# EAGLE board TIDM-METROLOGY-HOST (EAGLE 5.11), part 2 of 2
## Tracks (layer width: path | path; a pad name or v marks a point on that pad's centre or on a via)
+12V  (via drill 0.5)
  Top 0.254: R30.2 17.35,44.13 17.27,44.2 C53.1 18.87,44.28 20.32,45.73 21.71,45.73 21.96,45.97 21.96,46.62 21.84,46.74 C15.+
  Top 0.406: R30.2 17.53,41.92 17.34,41.73 T1.E 16.59,39.46 16,38.87 16,37.09 17.27,35.82 27.71,35.82 29.09,37.2 29.09,38.23 29.08,38.23 | 29.08,38.23 28.96,38.36 | 29.08,38.23 U2.8 | D3.2 20.07,53.35 19.66,52.94 D4.2 19.66,51.72 v18.54,52.84 | 22.1,46.74 C15.+ v19.71,46.73
  Bottom 0.406: v18.54,52.84 18.54,47.76 v19.71,46.73
+12V1
  Top 0.406: CON1.7 10.67,50.55 11.94,51.82 11.94,55.63 12.19,55.89 14.73,55.89 15.49,55.12 22.61,55.12 22.86,54.87 22.86,53.6 23.11,53.35 24.38,53.35 24.41,53.32 D3.1
+12V3
  Top 0.406: CON1.4 13.21,54.62 14.82,54.62 16.4,53.04 16.4,51.43 16.51,51.31 16.38,51.19 D4.1
-12V  (via drill 0.5)
  Top 0.254: C53.2 18.03,46.16 18.03,45.98 18.64,45.38 v18.64,45.34 | R31.1 21.92,41.59 v21.34,42.17 | D7.1 21.31,48.49 21.84,49.03 21.84,50.04 C22.-
  Top 0.406: R31.1 25.83,41.59 25.91,41.66 25.98,41.59 R28.2 26.16,41.66 26.54,42.04 U2.5 | C53.2 17.96,46.16 18.8,47 18.8,48.27 18.92,48.39 D7.1
  Bottom 0.254: v21.34,42.17 20.57,42.17 v18.64,45.34
A0CLK  (via drill 0.41, 0.5)
  Top 0.254: U1.17 21.88,70.4 23.88,72.4 28.57,72.4 28.96,72.78 v28.98,72.78 | R82.2 86.61,86.37 85.6,85.35 77.98,85.35 74.17,89.16 46.23,89.16 45.97,88.91 v45.97,88.65
  Bottom 0.254: v45.97,88.65 45.97,88.78 44.83,89.92 42.16,89.92 41.15,88.91 41.15,84.33 36.07,79.25 36.07,75.95 34.39,74.28 30.45,74.28 28.96,72.78 | 28.96,72.78 | v28.98,72.78 28.96,72.78
A0CS  (via drill 0.41, 0.5)
  Top 0.254: 73.91,77.22 73.89,77.25 v73.89,77.37 | 73.91,77.48 73.89,77.45 v73.89,77.37 | R81.2 88.39,85.63 87.22,84.46 83.07,84.46 83.04,84.49 83.02,84.46 v82.83,84.46 | v73.89,77.37 73.81,77.37 72.9,76.46 72.9,72.9 72.39,72.4 55.63,72.4 49.28,66.05 48.77,65.54 37.85,65.54 36.99,66.4 U1.51
  Bottom 0.254: v82.83,84.46 78.03,84.46 77.7,83.88 77.72,79 77.72,78.87 76.22,77.37 v73.89,77.37
A0SIMO  (via drill 0.6)
  Top 0.254: R106.1 80.52,100.84 v79.76,100.08 v79.76,91.19 79.76,87.13 80.52,86.37 84.33,86.37 84.84,86.87 R83.2 | R77.2 95.5,85.86 v96.77,84.59 | U1.21 22.92,68.4 24.89,70.36 32.77,70.36 33.53,71.13 33.53,74.68 v32.77,75.44 | v45.72,91.19 v77.72,91.19
  Bottom 0.254: v96.77,84.59 95.25,86.11 95.25,97.8 94.49,98.56 88.14,98.56 86.61,100.08 v79.76,100.08 | v32.77,75.44 34.54,75.44 35.05,75.95 35.05,79 40.64,84.59 40.64,89.41 41.66,90.43 44.96,90.43 v45.72,91.19 | v77.72,91.19 v79.76,91.19
A0SOMI  (via drill 0.5, 0.6)
  Top 0.254: U1.22 23.19,67.9 25.15,69.86 32.89,69.86 34.04,70.8 v34.04,76.67 | 83.06,87.38 R84.2 83.15,87.29 83.06,87.38 | v92.2,84.33 93.73,85.86 R78.2 93.73,87.64 | v77.22,87.38 74.93,89.67 45.21,89.67 44.2,90.68 v44.2,91.7 | R107.1 81.45,91.36 v81.53,87.38 83.06,87.38
  Bottom 0.254: v92.2,84.33 89.92,87.38 v81.53,87.38 v77.22,87.38 | v34.04,76.67 34.04,78.75 40.13,84.84 40.13,89.92 41.91,91.7 v44.2,91.7
ACT_PUL  (via drill 0.5)
  Top 0.254: U$1.P$17 48.73,26.71 47.75,27.69 47.75,30.36 v46.86,31.12
  Top 0.406: R75.1 48.77,49.28 48.26,48.77 ACT.1 48.24,47.52 47.48,47.52 45.21,45.25 LED1.K
  Bottom 0.406: LED1.K 43.94,42.93 41.4,42.93 40.13,41.66 40.13,37.34 41.15,36.33 COMMS.8 42.93,33.79 45.59,31.12 v46.86,31.12
AFE_INT  (via drill 0.5)
  Top 0.254: U$1.P$18 49.4,26.04 48.62,26.06 47.12,27.56 47.12,29.6 v46.81,29.84 | ISO3.7 63.12,49.15 v62.74,48.77 | v62.48,37.6 62.47,40.75 v62.22,41
  Bottom 0.254: v62.48,37.6 60.2,39.63 53.34,39.63 51.82,38.11 51.82,30.99 50.67,29.85 46.99,29.85 46.98,29.84 v46.81,29.84 | v62.22,41 62.22,41.02 62.23,41.03 64.64,41.03 65.53,41.92 65.53,48.27 65.02,48.77 v62.74,48.77
AGND_AFE  (via drill 0.41, 0.5, 0.6)
  Top 0.406: R33.1 R34.2 | JMP1.1 91.19,16.26 90.93,16.52 C33.1
  Top 0.813: R47.2 42.42,12.45 42.51,12.54 | 42.51,12.54 R53.1 33.11,9.4 R24.1 | C14.1 42.51,15.08 42.67,14.99 42.51,14.9 42.51,12.54
  Bottom 0.254: 63.5,22.1 v63.5,30.99
  other vias: 64.52,16.01 83.57,15.25 38.1,14.99 42.42,19.56 46.48,2.29 46.48,9.66 58.67,19.56 58.67,16.26 72.9,16.26 77.22,16.01 78.49,2.8 69.85,1.02 57.15,1.28 95.76,1.28 95.25,11.94 98.81,17.28 86.87,18.55 69.85,24.64 60.2,27.06
  pour Top: 36.07,0.01 36.07,20.71 54.86,20.71 54.83,29.81 59.01,29.93 59.69,30.74 61.98,34.3 62.74,34.3 71.04,26 71.08,24.98 71.12,21.85 84.84,21.85 88.65,18.29 100.58,18.29 100.58,13.47 97.28,13.47 97.03,0.26
  pour Bottom: 36.07,0.26 36.07,20.58 55.37,20.58 55.37,29.98 58.93,29.72 60.96,32.52 61.98,34.04 63.5,34.04 70.87,26.17 70.99,23.88 71.12,21.85 85.09,21.85 88.65,18.29 99.82,18.29 99.82,14.23 96.77,14.23 97.03,0.26
AGND_APP
  Top 0.254: U1.15 21.86,71.4 22.35,71.89 22.35,72.4 21.84,72.9 | 21.84,72.9 21.08,72.9 21.07,72.9 U1.12 18.8,72.9 17.14,74.94 16,74.94 C32.- 15.88,75.31 15.58,75.61 C35.1 13.72,75.7 8.64,75.7 8.25,76.08 8.25,77.09 8.22,77.13 R4.2 | U1.83 30.95,79.32 30.48,79 28.96,79 27.43,77.48 26.16,77.48 22.02,73.05 21.84,72.9
APP_INT  (via drill 0.5)
  Top 0.254: U1.34 26.45,63.79 v26.09,63.1 | 63.25,55.38 63.25,56.39 63.19,56.45 ISO3.2 63.12,58.93 63.12,61.47 | 63.12,61.47 63.12,61.6 64.01,62.49 64.01,64.01 COMMS_APP.2 | v56.39,57.41 56.39,59.7 57.66,60.97 62.48,60.97 62.99,61.47 63.12,61.47
  Bottom 0.254: v26.09,63.1 26.19,63.1 26.29,63 26.39,63.1 27.68,63.1 32.61,58.17 55.88,58.17 56.39,57.66 v56.39,57.41
AVCC_AFE  (via drill 0.6)
  Top 0.254: U$1.P$5 61.59,24.76 63.5,26.68 C12.2
  Top 0.305: v67.56,27.05 C11.+ | 67.69,27.05 69.09,28.45 69.09,30.57 R2.2
  Top 0.406: C11.+ 65.41,27.05 65.11,27.35 C12.2
  Top 0.61: D22.C 53.34,9.91 v52.07,11.18 | v66.29,7.37 65.45,6.53 D24.C | D26.C 75.44,11.18 v74.68,11.94 | D28.C 87.04,8.64 v85.09,8.64 | v67.56,27.05 67.69,27.05
  Bottom 0.61: v52.07,11.18 55.88,7.37 v66.29,7.37 70.1,7.37 74.68,10.42 | v85.09,8.64 76.45,8.64 74.68,10.42 | 74.68,10.42 v74.68,11.94 74.68,13.47 74.42,17.02 74.42,18.8 71.37,21.85 71.37,24.9 70.36,25.91 68.7,25.91 v67.56,27.05
AVCC_APP
  Top 0.254: U1.11 19.57,73.4 19.3,73.67 19.3,76.21 17.53,77.98 | C35.2 14.06,77.31 14.99,78.24 16,78.24 C32.+ 16.64,78.11
  Top 0.61: R3.2 18.45,78.91 17.53,77.98 16,77.98 C32.+
CCA  (via drill 0.5)
  Top 0.254: U1.39 28.95,62.98 30.48,62.24 41.66,62.24 43.43,64.01 50.04,64.01 50.29,64.27 54.61,68.59 v77.47,68.59 | R79.2 91.95,86.87 v92.71,86.11
  Bottom 0.254: v92.71,86.11 94.23,84.59 94.23,73.16 90.17,69.09 77.98,69.09 v77.47,68.59 77.34,68.46
COM0  (via drill 0.41, 0.5)
  Top 0.254: U1.30 24.45,66.62 25.91,68.08 v30.1,67.98 | v66.04,98.56 65.79,98.56 65.28,98.05 45.72,98.05 41.4,93.73 41.4,89.67 42.42,88.65 v43.18,88.65
  Bottom 0.254: v30.1,67.98 30.1,68.71 31.11,69.73 31.37,69.98 35.18,69.98 36.58,71.51 36.58,79 41.66,84.08 41.66,88.02 42.29,88.65 v43.18,88.65 | LCD1.P$18 66.29,98.81 v66.04,98.56
COM1  (via drill 0.41, 0.5)
  Top 0.254: U1.31 24.95,66.1 25.91,67.06 30.99,67.06 v31.62,67.59 | v67.56,98.05 67.06,98.05 66.29,97.29 45.97,97.29 42.16,93.48 42.16,90.43 42.93,89.67 43.69,89.67 44.07,89.11 44.08,87.64 v44.7,87.28
  Bottom 0.254: v44.7,87.28 44.7,84.84 38.1,78.24 38.1,70.62 35.08,67.59 v31.62,67.59 | LCD1.P$17 68.83,99.32 v67.56,98.05
COM2  (via drill 0.41, 0.5)
  Top 0.254: U1.32 25.45,65.84 26.16,66.55 32.26,66.55 32.77,67.06 32.77,68.08 v32.26,68.59 | 44.96,99.32 40.39,94.75 40.39,87.64 41.66,86.37 v43.18,86.37 | 44.96,99.32 45.47,99.83 | v71.37,99.32 71.12,99.32 70.36,100.08 45.72,100.08 44.96,99.32
  Bottom 0.254: v32.26,68.59 32.77,68.08 33.63,68.11 34.83,68.11 37.59,70.87 37.59,78.49 43.18,84.08 v43.18,86.37 | v71.37,99.32 LCD1.P$16
COM3  (via drill 0.41, 0.5)
  Top 0.254: U1.33 25.95,65.58 26.42,66.05 32.51,66.05 33.53,67.06 33.53,68.84 33.27,69.09 v33.33,69.09 | 45.21,98.56 45.72,99.07 | v71.88,96.53 68.83,99.57 46.23,99.57 45.21,98.56 | v43.24,87.53 41.77,87.53 40.89,88.4 40.89,94.24 45.21,98.56
  Bottom 0.254: LCD1.P$15 73.91,98.56 v71.88,96.53 | v33.33,69.09 35.05,69.09 37.08,71.25 37.08,78.75 42.16,83.83 42.16,87.13 42.55,87.51 43.05,87.51 43.07,87.53 v43.24,87.53
D+  (via drill 0.5)
  Top 0.254: USB2.3 13.13,89.49 v12.45,90.18
  Bottom 0.254: R7.2 9.65,89.16 9.69,89.12 IC7.4 9.84,89.23 9.8,89.26 9.86,89.31 9.86,89.92 10.11,90.18 v12.45,90.18
D-
  Bottom 0.254: 10.92,86.37 R35.2 10.92,86.11 10.89,86.15 IC7.1 10.92,88.14 11.43,88.14 11.96,88.73 14.73,88.73 15.13,88.26 USB2.2
DGND_AFE  (via drill 0.3, 0.41, 0.5)
  Top 0.254: v73.66,48.77 C52.1
  Top 0.406: ZD1.1 18.41,30.1 19.3,29.22 22.86,29.22 23.11,28.96 23.19,29.04 C26.1
  Top 0.61: 17.65,24.92 17.6,26.17 17.78,26.42 18.32,26.97 IC3.3 | 17.65,24.92 C25.1 | IC3.3 22.13,26.97 22.1,26.93 | IC3.3 IC3.2 23.11,28.96 23.37,29.22 C26.1 23.11,29.22 23.11,30.49 23.88,31.25 27.18,31.25 27.94,30.49 C23.- | 17.65,24.92 17.61,24.87 ZD2.1 14.2,24.87 13.46,24.14 | R1.1 11.18,17.02 13.46,19.31 13.46,21.85
  Top 0.813: R26.1 21.42,12.62 C4.- 14.61,13.21 R1.1
  Bottom 0.254: v73.66,48.77 73.41,48.77 72.9,49.28
  other vias: 42.16,55.63 76.96,26.93 74.17,51.31 96.77,35.31 19.05,28.96 76.96,35.57 67.06,50.55 54.86,46.23 35.56,25.66 41.66,33.79 47.5,55.63 31.24,34.8 35.31,50.55 41.4,40.65 36.07,37.09 70.74,28.96 50.42,32.01 50.42,33.15 59.69,41.05 60.2,36.33 61.72,39.38 91.19,24.39
  pour Top: 9.14,21.34 9.14,34.55 29.97,34.8 31.24,36.84 31.24,57.41 59.18,57.28 59.18,54.62 78.49,54.87 78.23,49.79 69.6,49.54 69.6,40.77 87.88,40.9 87.88,43.19 99.82,43.19 99.95,38.23 99.82,19.06 88.9,19.06 85.09,22.61 78.36,22.61 72.01,22.74 71.88,26.42 62.87,35.31 61.98,35.31 58.93,31.25 54.1,30.99 54.1,21.34
  pour Bottom: 9.14,21.34 9.14,34.55 31.24,34.55 31.24,57.41 59.05,57.41 59.05,54.36 78.1,54.23 77.85,51.57 69.47,47.63 69.6,41.15 86.87,41.15 86.87,43.19 99.82,43.19 100.08,19.31 88.65,19.31 85.34,22.61 71.88,22.87 71.88,26.42 71.12,26.93 70.87,27.18 64.14,34.5 63.63,35.01 62.48,35.06 61.72,34.8 58.17,30.74 54.1,30.74 54.1,21.34
DGND_APP  (via drill 0.3, 0.41, 0.5, 0.6)
  Top 0.254: U1.90 27.45,81.56 28.08,82.43 28.09,83.27 26.04,84.76 26.04,85.22 26.16,85.35 | 26.16,85.35 26.58,85.77 | C45.1 94.07,69.69 94.74,70.36 94.74,71.38 C44.- | C20.- 20.32,60.46 | 26.16,85.35 C7.-
  other vias: 2.03,76.46 18.57,74.43 19.3,58.43 97.28,69.6 90.8,67.82 30.28,76.66 74.68,93.99 85.85,74.17 73.41,86.87 53.59,93.73 56.13,93.73 58.42,93.73 90.93,84.08 65.28,83.32 44.9,88.38 37.08,88.65 21.43,81.14 31.5,86.11 47.5,98.81 18.54,92.97 37.85,104.15 22.18,74.45 75.79,69.4 33.91,66.17 31.88,73.41 73.13,61.14 77.72,63.76 65.74,57.05 45.97,72.65 52.32,60.97 57.91,58.2
  pour Top: 100.08,100.59 88.9,100.59 88.9,112.02 10.92,112.02 10.92,100.84 0.25,100.84 0.25,68.84 16,68.84 16,57.54 30.61,57.54 30.61,58.17 59.82,58.17 59.79,56.16 68.58,56.14 80.01,55.89 85.85,60.2 100.33,60.2
  pour Bottom: 0.32,100.83 0.32,69.08 15.75,69.09 15.75,55.89 27.18,55.89 31.24,58.68 31.75,58.17 60.1,58.17 60.05,55.02 68.07,55.12 78.74,54.87 85.85,60.2 100.33,60.2 100.33,100.84 88.9,100.84 88.9,112.02 10.92,112.02 10.92,100.83
DVCC_AFE  (via drill 0.5, 0.6)
  Top 0.254: 79.12,52.96 ISO2.8 79.12,51.95 76.96,49.79 76.96,49.03 77.05,48.94 C52.2 | U$1.P$16 51.38,27.36 50.67,28.07 50.67,28.45 | ISO3.8 64.39,53.66 64.38,53.67 64.39,53.69 64.39,53.73 66.29,55.58 70.13,55.58 70.99,54.74 70.99,53.47 71.12,53.35 | ISO1.8 71.06,52.78 71.12,52.84 71.12,53.35 | C55.2 71.21,53.43 71.12,53.35
  Top 0.305: DVCC1.4 72.64,33.79 75.95,30.49 v76.45,30.14 76.45,28.96 75.44,27.95 72.39,27.95 71.88,28.45 71.88,29.81 R2.1
  Top 0.406: 85.85,25.91 JTG_PWR1.2 85.76,24.81 R61.1 | 39.62,49.79 39.62,50.3 39.29,50.63 C54.2 R39.1 36.91,48.7 36.83,48.77 36.07,48.77 35.69,49.15 U5.8 32.89,49.15 32.26,49.79 32.26,52.08 R73.2 | v49.1,27.62 48.9,27.56 48.9,28.45 | 41.31,28.2 v42.07,28.08 | 64.39,53.73 59.82,53.73 59.44,54.11 57.4,54.11 56.13,52.84 45.72,52.84 | 41.91,47.76 R72.2 | 45.72,52.84 44.96,52.84 OK2.1 | 41.4,49.79 44.96,49.79 45.97,50.81 45.97,52.58 45.72,52.84 | 48.9,28.45 48.77,29.22 C9.+ 48.77,28.45 48.9,28.45 | C10.2 50.67,28.45 48.9,28.45 | C55.2 72.9,54.36 73.66,55.12 78.74,55.12 79.12,54.74 79.12,52.96
  Top 0.61: PWR1.2 41.31,26.69 41.31,28.2 41.31,32.61 38.64,35.28 38.64,39.09 38.61,39.12 38.65,39.16 R37.1 38.65,41.96 v39.12,42.42 | v40.13,44.71 40.13,45.47 41.91,47.25 41.91,47.76 41.91,49.03 41.4,49.79 39.62,49.79 R27.2 | DVCC1.4 DVCC1.3 DVCC1.2 DVCC1.1 | C52.2 77.05,48.86
  Bottom 0.305: v76.45,30.14 76.2,30.49
  Bottom 0.406: JTG_PWR1.2 86.61,25.66 | v42.07,28.08 46.48,28.07 48.26,28.07 v49.1,27.62 | OK1.1 51.56,47 48.77,49.79 48.77,52.58 47.24,54.11 OK2.1
  Bottom 0.61: v40.13,44.71 39.12,43.69 v39.12,42.42 | 49.22,27.49 49.15,27.56 | v49.1,27.62 49.22,27.49 | 49.22,27.49 49.53,27.31 55.12,27.31 57.66,29.85 58.93,29.85 61.6,32.52 65.02,32.52 | 65.02,32.52 80.64,32.52 82.55,30.61 82.55,27.95 84.58,25.91 JTG_PWR1.2 | 65.02,32.52 DVCC1.1
DVCC_APP  (via drill 0.41, 0.5, 0.6)
  Top 0.254: 27.94,80.52 27.95,80.52 U1.89 27.95,81.04 28.96,82.05 v28.96,82.81 | C7.+ 28.7,85.35 28.28,85.77 C8.2 | 20.19,63.38 C20.+ 20.32,63.51 | 20.32,63.51 20.65,63.84 20.65,66.35 U1.25 20.65,63.83 20.32,63.51 | C21.2 18.63,62.83 18.8,63 19.3,63.51 20.32,63.51 | RF4.9 92.07,68.46 92.46,68.84 92.37,68.93 C45.2 92.37,69.69 91.69,70.36 91.69,71.13 91.82,71.25 C44.+ | R3.1 20.15,81.37 20.07,81.29 20.22,81.13 | 28.83,85.27 28.27,85.83 28.27,87.56 28.19,87.64 | v43.43,75.44 43.18,75.44 40.63,72.9 U1.64 | ISO1.1 71.06,57.98 71.21,57.83
  Top 0.406: 92.46,68.84 92.46,68.08 92.96,67.57 99.57,67.57 100.08,67.06 100.08,60.97 99.06,59.95 82.8,59.95 80.83,57.98 | 80.83,57.98 ISO2.1 79.19,57.98 79.25,57.92 79.12,57.79 79.12,56.55 78.71,56.14 73.91,56.14 73.15,56.9 | 28.83,85.27 28.83,82.94 v28.96,82.81 | ISO3.1 64.39,56.27 64.52,56.14 72.39,56.14 73.15,56.9 | 80.77,59.7 C50.2 80.77,57.98 80.83,57.98 | 73.15,56.9 C2.2 71.21,57.83
  Top 0.61: 28.19,87.64 C8.2 28.28,89.25 v28.45,89.41 | 91.69,71.13 90.42,71.13 v89.92,71.89 | 18.8,63 16.51,63 16,62.49 16,57.92 17.27,56.9 29.21,56.9 30.99,58.68 | 30.99,58.68 31.24,58.93 | v84.58,72.4 83.82,73.16 75.69,73.16 75.18,72.65 v75.18,72.4 | 20.07,81.79 20.07,80.27 v20.32,80.02 | v48.57,61.07 48.51,60.2 47.75,59.44 31.75,59.44 30.99,58.68 | R14.1 17.44,85.44 20.07,82.81 20.07,81.79 | 20.07,81.79 20.15,81.71 R3.1
  Bottom 0.254: 41.66,74.17 41.55,74.28
  Bottom 0.406: 41.55,74.28 42.27,74.28 v43.43,75.44
  Bottom 0.61: v28.45,89.41 28.45,91.19 30.99,93.73 30.99,96.27 33.4,98.68 DVCC2.2 37.34,98.56 | 89.66,72.14 v89.92,71.89 89.92,72.14 89.66,72.4 v84.58,72.4 | 48.26,72.4 v75.18,72.4 | 48.26,72.4 47.24,73.41 | 47.24,73.41 46.65,74.01 C6.2 41.82,74.01 41.66,74.17 C5.+ | 48.26,72.4 48.51,72.14 v48.57,61.07 | 47.24,73.41 47.24,95.38 44.2,98.43 37.47,98.43 37.34,98.56 | 37.34,98.56 DVCC2.1 39.8,103.43 39.8,108.72 | v20.32,80.02 27.69,80.02 28.96,81.29 v28.96,82.81 | 39.8,108.72 JTG_PWR2.2 | 39.8,108.72 PWR2.2
DVCC_APP_EXT
  Top 0.406: R15.1 35.18,95.38 34.29,96.53 34.29,101.35 34.8,101.86 34.8,102.11 35.81,103.13 38.86,103.13 PWR2.3
DVCC_APP_PL  (via drill 0.5, 0.6)
  Top 0.406: 87.88,75.95 ZD3.C 87.87,75.93 87.63,75.7 85.6,75.7 C36.+ | C37.1 82.55,81.03 82.3,80.78 77.47,80.78
  Top 0.61: v78.49,78.24 83.06,78.24 | 83.06,78.24 C36.+ | 82.3,80.78 82.3,79 83.06,78.24 | 77.47,80.78 v75.95,82.3 | v75.95,99.07 74.17,100.84 44.2,100.84 42.04,103 44.45,103 44.45,109.73 42.93,111.26 PWR2.1
  Bottom 0.61: U$2.VO+ 75.95,70.36 77.47,71.89 77.47,76.71 v78.49,78.24 | v75.95,99.07 76.2,98.81 75.95,98.56 v75.95,82.3
DVCC_FET1
  Bottom 0.61: JTG_PWR1.1 96.27,23.37 98.3,25.41 98.3,37.09 97.03,38.36 81.53,38.36 JTAG1.2
DVCC_FET2
  Top 0.406: JTAG2.2 32.26,100.34 32.26,109.73 33.78,111.26 JTG_PWR2.1
DVCC_PL
  Top 0.406: IC3.5 24.35,24.35 24.56,24.57 R23.2
  Top 0.61: IC3.5 24.6,24.35 25.15,24.9 25.15,28.96 25.07,29.04 C26.2
  Top 0.813: C26.2 25.74,28.45 28.96,28.45 29.97,29.47 29.97,33.28 29.72,33.53 | 29.72,33.53 27.69,33.53 | 27.69,33.53 27.51,33.53 C23.+ | ZD1.2 22.45,33.53 27.69,33.53 | PWR1.1 33.27,33.53 29.72,33.53
GND1
  Top 0.406: C22.+ 24.64,50.04 24.77,49.91 C15.- 24.64,46.74 24.77,46.61 U5.3 30.35,46.61 30.73,47 30.73,51.06 30.1,51.69 D1.1 30.2,51.8 30.23,51.82 30.09,51.96 30.09,55.07 29.17,55.98 16.33,55.98 15.09,57.23 15.09,57.31 CON1.5
  Bottom 0.813: CON1.G1 11.94,39.12 7.62,39.12 5.08,42.68 5.08,59.95 9.47,64.34 CON1.G2 11.94,64.52 13.21,63.25 CON1.5
HFIN
  Top 0.254: Q1.2 Q1.4 32.51,85.1 30.45,83.03 U1.84
  Bottom 0.406: Q1.4 32.77,85.22 33.66,84.84 C48.1
HFOUT
  Top 0.254: U1.85 29.95,84.06 30.73,84.84 30.73,87.13 31.75,88.14 32.77,88.14 Q1.1 Q1.3
  Bottom 0.254: 36.83,92.21 C47.1
  Bottom 0.406: 36.83,92.21 34.16,92.21 32.77,90.81 Q1.3
I1+
  Top 0.254: C30.1 63.5,22.87 63.25,22.61 | U$1.P$1 61.92,22.16 62.48,21.6 63.25,21.6 63.75,22.1
  Top 0.406: 62.99,20.33 C17.1 | R17.1 63.08,20.24 62.99,20.33 | 62.99,20.33 62.99,21.34 63.75,22.1 63.75,22.87 C30.1
I1-
  Top 0.254: 65.28,22.87 65.37,22.96 | 65.35,23.19 65.28,23.12 65.37,23.03 C30.2 65.28,22.87 | U$1.P$2 62.06,22.81 63.03,23.79 65.1,23.76 65.35,23.52 65.35,22.93 65.28,22.87
  Top 0.406: R18.1 65.7,19.98 65.79,20.07 65.7,20.16 C18.2 65.7,20.49 65.79,20.58 65.37,21 C30.2
IN+
  Top 0.254: 82.8,19.06 72.14,19.06 66.53,24.76 63.31,24.76 61.98,23.46 U$1.P$3
  Top 0.406: R20.2 82.13,14.4 82.04,14.48 82.04,16.52 C31.1 82.13,17.62 82.8,18.29 82.8,19.06 C34.1
IN-
  Top 0.254: 84.33,19.06 C34.2 85.34,19.06 85.6,19.31 85.6,19.82 85.09,20.33 71.88,20.33 66.8,25.41 63.25,25.41 61.84,24.1 U$1.P$4
  Top 0.406: R21.2 85,16.17 85.09,16.26 85,16.35 C33.2 85.09,16.52 85.09,17.79 84.42,18.46 C34.2
L_APP
  Top 0.813: U$2.L 87.63,52.58 82.3,47.25 82.42,47.12 R5.2 85.72,47.12 89.15,50.55 90.93,50.55 91.44,51.06 91.44,55 92.84,56.39 L2.MP
LCDCAP
  Top 0.254: U1.29 23.95,62.42 24.89,61.47 25.4,61.47 C51.+
LINE
  Top 0.61: L1.MP 8.13,4.4 L5.1
LINE_A
  Top 0.61: R1.2 7.7,6.86 L5.2
  Top 0.813: R38.1 34.93,3.82 C49.1
  Bottom 0.813: R1.2 31.88,6.86 C49.1
M_SIMO  (via drill 0.41, 0.7)
  Top 0.254: U1.18 22.14,69.9 24.13,71.89 30.23,71.89 v30.86,72.52 | ISO2.3 v76.58,60.46 76.58,60.58 73.15,64.01 68.83,64.01 67.82,63 COMMS_APP.5
  Bottom 0.254: 76.58,60.33 v76.58,60.46 76.45,60.46 73.91,57.92 62.99,57.92 61.98,58.93 35.56,58.93 27.94,66.55 27.94,69.35 30.86,72.27 v30.86,72.52
M_SOMI  (via drill 0.41, 0.7)
  Top 0.254: U1.19 22.4,69.4 24.38,71.38 30.99,71.38 v31.95,72.24 | ISO2.2 77.85,60.2 v78.49,60.84
  Bottom 0.254: v31.95,72.24 31.9,72.29 28.45,68.84 28.45,67.06 36.07,59.44 62.23,59.44 63.25,58.43 65.79,58.43 70.1,62.74 COMMS_APP.7 76.71,62.74 78.49,60.97 v78.49,60.84
MSPI_CLK  (via drill 0.41, 0.5)
  Top 0.254: U1.20 22.66,68.9 24.64,70.87 32.26,70.87 v32.66,71.42 | v64.01,59.26 65.25,59.29 65.79,59.7 68.08,59.7 68.46,59.32 68.46,58.05 68.39,57.98 | 68.45,58.04 ISO1.3 68.39,57.98 | 68.39,57.98 68.33,57.92
  Bottom 0.254: v32.66,71.42 31.98,71.35 29.2,68.59 29.2,67.33 36.58,59.95 63.25,59.95 64.01,59.19 v64.01,59.26 | v64.01,59.26 63.75,59.26 63.5,59.44 | COMMS_APP.3 65.28,60.46 v64.01,59.26
MSPI_CS  (via drill 0.5)
  Top 0.254: U1.35 26.95,61.7 30.23,60.2 42.67,60.2 44.45,61.98 61.98,61.98 COMMS_APP.1 | ISO1.2 69.72,59.57 69.09,60.2 64.77,60.2 v64.26,60.71
  Bottom 0.254: v64.26,60.71 64.26,61.22 COMMS_APP.1
N$1
  Top 0.61: L6.2 18.89,3.99 R26.2
N$2
  Top 0.406: R36.1 28.96,54.11 28.7,53.85 28.7,52.33 28.19,51.82 D1.2 26.67,51.82 26.67,48.27 27.05,47.88 U5.2
N$3
  Top 0.406: R28.1 26.16,39.63 26.29,39.5 U2.7
N$4
  Top 0.406: R29.1 29.46,44.2 30.73,42.93 30.73,41.02 30.5,40.78 29.33,40.78 29.21,40.9 29.15,40.84 U2.6
N$5
  Top 0.406: T1.C 18.46,37.26 18.67,37.47 R32.2
N$6
  Top 0.254: RF3.9 92.07,97.92 91.69,98.3 83.65,98.3 R107.2
N$7
  Top 0.254: RF4.15 88.27,66.93 87.02,68.18 87.02,68.74 87.12,68.84 87.06,68.9 R87.1
N$8
  Top 0.254: T2.B 37.02,33.85 37.67,33.2 R40.2
N$9
  Top 0.406: JTAG2.4 29.97,97.03 31.75,97.03 33.53,98.81 33.53,104.65 35.05,106.18 JTG_PWR2.3
N$10
  Top 0.813: USB2.6 10.43,80.76 10.41,80.78 10.43,80.79 USB2.5
  Bottom 0.254: R9.2 7.53,85.01 6.35,83.83 6.35,81.41 7.4,80.37 USB2.6
N$11
  Top 0.254: C46.1 23.03,60.8 22.86,60.97 22.95,61.05 U1.27
N$12
  Top 0.406: C38.- 91.95,77.22 88.9,74.17 U$2.26
N$13  (via drill 0.5)
  Top 0.406: C38.+ 92.46,82.3 78.74,82.3 v78.71,82.48
  Bottom 0.406: U$2.22 78.74,76.21 79.76,77.22 79.76,81.29 v78.71,82.48
N$19
  Top 0.813: CUR1+.MP D22.A 55.63,5.67 | D23.C 57.15,5.59 57.07,5.67 55.63,5.67 | 55.63,5.67 55.63,6.86 56.66,7.9 L15.1 56.66,11.93 55.88,12.71 D32.2
N$20
  Top 0.813: CUR1-.MP 61.72,2.29 62.56,3.13 D24.A 67.99,3.13 68.07,3.05 68.15,3.13 D25.C 68.07,3.31 68.07,4.83 67.58,5.32 L16.1 67.56,6.1 67.56,7.88 66.55,8.9 61.21,8.9 59.18,10.93 D32.1
N$21
  Top 0.813: 75.69,5.09 75.61,5.16 D26.A 75.26,5.16 75.18,5.09 73.41,5.09 72.02,6.48 D33.2 | CUR2+.MP 75.44,4.83 75.69,5.09 | 75.69,5.09 D27.C 79.58,7.45 80.03,7.9 L17.1
N$22  (via drill 0.8)
  Top 0.813: D33.1 78.23,11.44 v78.23,7.37 | L18.1 91.95,6.86 91.95,5.59 91.01,4.66 D29.C 87.88,3.82 | D28.A 87.12,4.58 87.88,3.82 | 87.88,3.82 87.88,2.29 CUR2-.MP
  Bottom 0.813: v78.23,7.37 78.23,6.61 83.06,1.78 CUR2-.MP
N$24
  Top 0.406: R19.2 86.11,11.44 86.87,12.2 86.87,13.72 86.61,13.98 R21.1 90.68,13.98 90.93,13.72 JMP1.2
  Top 0.813: L18.2 93.96,9.17 91.19,11.94 JMP1.2
N$26
  Bottom 0.813: R22.1 6.35,19.56 30.73,19.56 33.78,22.61 C49.2
N$27
  Top 0.406: 66.04,11.18 R16.1 | 66.04,11.18 66.55,11.18 67.31,11.94 67.31,14.48 67.4,14.57 R34.1 67.4,17.19 67.31,17.28 67.4,17.37 R18.2 | L16.2 69.58,9.67 68.07,11.18 66.04,11.18
N$29
  Top 0.813: ZD2.2 11.81,24.87 D10.1 11.68,22 10.06,22 7.87,19.82 7.87,17.79 R22.2
N$30
  Top 0.406: T1.B 19.24,41.85 19.3,41.92 | R29.2 19.77,44.2 19.24,43.68 19.24,41.98 19.3,41.92 | 19.3,41.92 R30.1
N$31
  Top 0.406: L17.2 83.31,8.13 83.48,8.3 R19.1 81.28,11.44 80.52,12.2 80.52,13.72 80.43,13.81 R20.1
N$32
  Top 0.813: R50.1 R44.2 44.36,9.19 44.32,9.28 44.36,9.36 R53.2
N$39
  Top 0.813: R38.2 R41.1
N$42
  Top 0.406: L15.2 58.66,9.17 57.66,10.17 57.66,13.98 58.42,14.74 60.96,14.74 61.21,14.99 | 61.21,14.99 61.38,14.83 R33.2 61.38,11.78 61.98,11.18 R16.2 | R17.2 61.47,17.53 61.21,17.28 61.21,14.99
N$49
  Top 0.406: R37.2 36.68,39.27 36.45,39.5 U2.2
N$51
  Bottom 0.254: USB2.1 15.01,85.12 13.34,83.44 D2.1
N$52
  Top 0.254: RF3.3 95.88,99.45 95.25,100.08 88.9,100.08 87.88,101.1 87.88,103.38 87.12,104.15 85.69,104.15 R108.2
N$56
  Top 0.254: RF3.6 94.61,91.57 95.5,90.68 R77.1 95.5,89.16
N$57
  Top 0.254: RF3.8 93.34,90.81 93.73,90.43 R78.1 93.73,89.16
N$58
  Top 0.254: RF3.10 92.07,90.81 91.95,90.68 R79.1 91.95,89.16
N$60
  Top 0.254: RF3.12 90.8,91.06 90.17,90.43 R80.1
N$61
  Top 0.254: RF3.14 89.53,91.57 88.39,90.43 R81.1 88.39,89.16
N$62
  Top 0.254: RF3.16 88.27,91.83 86.61,90.18 R82.1
N$63
  Top 0.254: RF3.18 86.99,92.33 84.84,90.18 R83.1 84.84,89.16
N$64
  Top 0.254: RF3.20 84.84,93.22 83.06,91.45 R84.1
N$65
  Top 0.254: RF4.18 86.99,62.62 87.12,62.49 87.12,61.73 86.61,61.22 82.55,61.22 80.64,63.12 R85.2
N$104
  Top 0.406: LED1.A 42.67,45.22 43.69,46.23 44.99,46.23 45.33,46.58 45.33,47.64 45.21,47.76 R72.1
N$105
  Top 0.406: R73.1 33.87,53.77 LED2.A
N$108
  Top 0.254: RF4.19 85.72,67.29 85.42,67.59 85.42,68.76 85.34,68.84 R86.1
N$109
  Top 0.406: OK1.4 HDR1.1
N$110
  Top 0.254: RF3.5 94.61,98.94 93.98,99.57 88.39,99.57 87.12,100.84 87.12,102.11 86.61,102.62 R105.2
N$111
  Top 0.254: RF3.7 93.34,98.68 92.96,99.07 87.38,99.07 85.85,100.59 85.94,100.59 R106.2
N$113
  Top 0.406: R76.2 43.18,52.08 OK2.2
N$114
  Top 0.406: R75.2 55.12,49.28 56.13,48.27 56.13,44.96 55.63,44.46 OK1.2 52.32,44.2
N$117
  Top 0.406: OK1.3 HDR1.2
N$118
  Top 0.406: OK2.4 HDR2.1
N$119
  Top 0.406: OK2.3 HDR2.2
N$130
  Bottom 0.305: JTAG1.4 83.57,35.31 83.57,32.52 86.87,29.22 JTG_PWR1.3
N$455
  Top 0.254: T2.E 32.58,35.75 32.26,36.07 32.26,40.39 32.64,40.77 U2.3
N_APP
  Top 0.813: N2.MP 93.98,47.5 93.22,46.74 87.63,46.74 84.71,43.82 R5.1 72.39,44.46 73.66,45.73 76.96,45.73 U$2.N
NEUTRAL
  Top 0.61: L6.1 17.53,2.8 18.29,2.04 N1.MP R24.2
PU.0/DP  (via drill 0.5)
  Top 0.254: U1.77 33.95,78.4 29.21,73.67 v27.94,73.67
  Bottom 0.254: 5.84,88.91 R25.2 5.84,87.13 5.75,87.22 C39.1 3.56,87.13 2.54,87.13 2.03,86.62 2.03,82.17 9.02,75.19 26.42,75.19 v27.94,73.67 | R6.2 4.45,89.54 4.83,89.16 R7.1
  Bottom 0.406: 5.84,88.91 6.01,89.07 R7.1
PU.1/DM  (via drill 0.5)
  Top 0.254: U1.79 32.95,78.93 31.93,77.91 30.38,77.91 v28.7,76.46
  Bottom 0.254: C40.1 10.67,83.06 10.64,83.17 | v28.7,76.46 17.27,76.41 10.64,83.17 | 10.64,83.17 10.64,83.29 10.92,83.57 R35.1
PUR  (via drill 0.5)
  Top 0.254: U1.78 33.47,78.64 29.46,74.66 26.92,74.68 v25.4,73.92
  Bottom 0.254: v25.4,73.92 25.15,73.67 13.97,73.67 12.95,74.68 8.13,74.68 1.02,81.79 1.06,81.83 1.07,81.83 1.02,81.92 1.02,84.21 | 1.02,84.21 1.02,82.68 | 1.02,84.21 1.02,92.59 1.36,92.93 R6.1
REACT_PUL  (via drill 0.5)
  Top 0.254: U$1.P$12 58.39,29.31 58.43,29.36 58.44,29.34 59.05,29.34 59.69,29.98 59.69,30.66 62.36,33.33 62.36,36.33 57.79,40.9 47.24,40.9 46.74,40.39 46.74,38.61 45.47,37.34 COMMS.6
  Top 0.406: LED2.K 36.83,55.38 37.34,54.87 REACT.1 38.35,54.87 38.86,54.36 38.86,52.84 39.54,52.16 R76.1 | v39.88,35.82 39.88,37.34 v41.15,38.61
  Bottom 0.406: REACT.1 37.59,38.11 v39.88,35.82 | v41.15,38.61 41.15,38.11 41.66,37.6 44.45,37.6 45.47,36.58 COMMS.6
RESET_AFE  (via drill 0.41)
  Top 0.254: U$1.P$11 59.9,28.66 60.2,28.96 60.2,30.49 62.48,32.77 71.88,32.77 73.91,30.74 73.91,29.39 S4.1 | R61.2 84.42,26.51 85.09,27.18 89.15,27.18
  Top 0.305: 83.57,26.42 83.16,26.02 S4.2 | C27.1 89.15,21.43 89.15,27.18
  Top 0.406: R61.2 83.57,26.42 83.82,26.68 v83.82,28.71
  Bottom 0.254: S4.1 74.83,29.32 75.18,28.96 79.5,28.96 S4.2
  Bottom 0.305: 83.82,30.99 JTAG1.1
  Bottom 0.406: v83.82,28.71 83.82,30.99
RESETCC  (via drill 0.5, 0.6)
  Top 0.254: U1.40 29.45,63.27 30.53,62.74 41.4,62.74 43.18,64.52 49.78,64.52 54.36,69.09 73.41,69.09 77.22,72.4 83.06,72.4 83.9,71.51 86.49,71.51 86.87,71.13 86.85,71.13 | 86.87,70.62 86.97,70.72 | v87.63,74.17 86.85,73.4 86.85,71.13 | v93.22,83.06 v98.3,83.06 98.55,83.06 | 86.87,70.62 86.88,70.6 R87.2 | 86.85,71.13 86.85,70.63 86.87,70.62 | R105.1 80.52,102.62 v80.01,102.11
  Bottom 0.254: v87.63,74.17 87.63,81.29 89.41,83.06 v93.22,83.06 | v80.01,102.11 86.11,102.11 88.9,99.32 95.5,99.32 96.27,98.56 96.27,87.38 98.3,85.35 v98.3,83.06
RF_GPIO1  (via drill 0.5)
  Top 0.254: U1.36 27.45,62.09 30.48,60.71 42.42,60.71 44.2,62.49 50.8,62.49 51.05,62.74 55.37,67.06 63.5,67.06 COMMS_APP.4 | R86.2 85.36,70.6 85.34,70.62 83.06,70.62 v78.74,66.3
  Bottom 0.254: v78.74,66.3 78.74,66.05 77.72,65.03 | 77.72,65.03 76.96,64.27 | COMMS_APP.4 65.28,64.78 66.04,64.01 76.71,64.01 77.72,65.03
RF_GPIO2
  Top 0.254: U1.37 27.92,62.41 30.48,61.22 42.16,61.22 43.94,63 50.55,63 51.05,63.51 55.12,67.57 65.53,67.57 COMMS_APP.6 70.1,67.57 75.69,67.57 78.23,65.28 80.52,65.28 80.64,65.16 R85.1 80.63,65.14 80.52,65.03 80.39,65.16
RST/NMI
  Top 0.254: U1.96 24.46,81.14 24.22,81.29 22.94,81.29 20.73,83.5 20.73,86.26 20.83,86.37 | 20.83,86.37 C24.2 | 20.83,86.37 20.83,96.27 19.3,97.8 19.3,100.08 JTAG2.11
  Top 0.406: C24.2 R14.2
RXD  (via drill 0.5)
  Top 0.406: D7.2 15.65,49.38 CON1.3 | R36.2 26.42,54.11 v25.65,54.87
  Bottom 0.406: v25.65,54.87 16.26,54.87 CON1.3
S0
  Top 0.254: LCD1.P$14 76.45,80.52 68.58,88.4 46.99,88.3 46.89,88.3 36.99,78.4 U1.75
S1
  Top 0.254: LCD1.P$13 73.91,81.29 67.56,87.64 46.99,87.64 37.25,77.9 U1.74
S2
  Top 0.254: LCD1.P$12 71.37,80.78 65.28,86.87 46.99,86.87 37.51,77.4 U1.73
S3
  Top 0.254: LCD1.P$11 68.83,81.29 64.01,86.11 46.99,86.11 37.77,76.9 U1.72
S4
  Top 0.254: LCD1.P$10 66.29,80.78 61.72,85.35 46.99,85.35 38.04,76.4 U1.71
S5
  Top 0.254: LCD1.P$9 63.75,81.79 60.96,84.59 46.99,84.59 38.3,75.9 U1.70
S6
  Top 0.254: LCD1.P$8 61.21,81.03 58.17,84.08 47.24,84.08 44.7,81.54 44.7,78.75 44.45,78.47 41.91,78.47 38.81,75.4 U1.69
S7
  Top 0.254: U1.68 39.08,74.9 42.16,77.98 46.48,77.98 47.24,78.75 47.24,83.06 47.75,83.57 56.64,83.57 58.67,81.54 LCD1.P$7
S8
  Top 0.254: 53.59,82.05 54.86,82.05 56.13,80.78 LCD1.P$6 | 53.59,82.05 53.34,82.05 | U1.67 39.34,74.4 42.42,77.48 48.77,77.48 49.78,78.49 49.78,81.29 50.55,82.05 53.59,82.05
S9
  Top 0.254: U1.66 39.85,73.9 42.93,76.97 51.05,76.97 LCD1.P$5
S10  (via drill 0.41)
  Top 0.254: U1.65 40.12,73.4 43.18,76.46 50.8,76.46 v51.05,76.08
  Bottom 0.254: v51.05,76.08 LCD1.P$4
S11  (via drill 0.41)
  Top 0.254: U1.62 40.9,71.9 44.55,75.16 v48.26,75.19
  Bottom 0.254: LCD1.P$3 48.51,75.44 v48.26,75.19
S12  (via drill 0.41)
  Top 0.254: v44.77,70.93 44.77,71.06 44.43,71.4 U1.61
  Bottom 0.254: LCD1.P$2 45.97,78.75 44.7,77.48 41.66,77.48 39.12,74.94 39.12,71.13 40.13,70.11 43.94,70.11 v44.77,70.93
S13  (via drill 0.41)
  Top 0.254: U1.60 39.35,70.9 40.13,70.11 45.47,70.11 v45.97,70.62
  Bottom 0.254: v45.97,70.62 45.97,70.11 45.47,69.6 39.88,69.6 38.61,70.87 38.61,75.19 41.4,77.98 43.18,77.98 43.43,78.24 LCD1.P$1
S14  (via drill 0.41)
  Top 0.254: U1.59 39.08,70.4 39.88,69.6 46.48,69.6 46.74,69.86 46.73,69.86 53.85,77.02 v61.49,77.02
  Bottom 0.254: LCD1.P$19 63.75,90.43 72.64,81.54 72.64,77.98 71.12,76.46 61.98,76.46 v61.49,77.02
S15  (via drill 0.41)
  Top 0.254: U1.58 38.82,69.9 39.62,69.09 46.74,69.09 46.99,69.35 53.85,76.21 62.23,76.21 62.74,76.71 v62.74,77.73
  Bottom 0.254: v62.74,77.73 63.25,77.22 69.09,77.22 70.1,78.24 70.1,83.32 62.99,90.43 62.99,100.59 LCD1.P$20
S16  (via drill 0.41)
  Top 0.254: U1.57 38.56,69.4 39.37,68.59 46.99,68.59 47.24,68.84 54.1,75.7 62.48,75.7 v65.02,78.24 65.02,78.11
  Bottom 0.254: v65.02,78.24 67.06,78.24 67.56,78.75 67.56,85.1 62.48,90.18 62.48,98.3 58.67,102.11 LCD1.P$21
S17  (via drill 0.41)
  Top 0.254: U1.56 38.3,68.9 39.12,68.08 47.24,68.08 47.5,68.33 54.36,75.19 67.82,75.19 68.14,75.51 v68.14,75.59 68.18,75.59 68.2,75.57
  Bottom 0.254: v68.14,75.59 61.19,75.59 60.81,75.59 60.45,75.95 60.45,77.22 62.48,79.25 62.48,89.41 61.98,89.92 61.98,96.53 LCD1.P$22
S18  (via drill 0.41)
  Top 0.254: U1.55 38.04,68.4 38.86,67.57 47.5,67.57 47.75,67.82 54.61,74.68 68.83,74.68 v69.34,75.19
  Bottom 0.254: v69.34,75.19 68.83,74.68 60.58,74.68 59.94,75.32 59.94,96.27 53.85,102.37 LCD1.P$23
S19  (via drill 0.41)
  Top 0.254: U1.54 37.77,67.9 38.61,67.06 47.75,67.06 48.01,67.32 54.86,74.17 69.85,74.17 v70.87,75.19 70.61,75.19
  Bottom 0.254: v70.87,75.19 69.6,74.17 59.18,74.17 57.4,76.46 57.4,96.02 LCD1.P$24 51.31,102.11 51.05,101.86
S20  (via drill 0.41)
  Top 0.254: U1.53 37.51,67.4 38.35,66.55 48.01,66.55 48.26,66.81 55.12,73.67 70.36,73.67 70.72,74.03 v70.86,74.03 70.85,74.03
  Bottom 0.254: 48.51,101.86 48.77,102.11 LCD1.P$25 48.77,102.37 54.86,96.27 54.86,77.48 58.67,73.67 70.49,73.67 70.86,74.03 | 70.86,74.03 70.86,74.04 | v70.86,74.03 70.86,74.03
S21  (via drill 0.41)
  Top 0.254: U1.52 37.25,66.9 38.1,66.05 48.26,66.05 48.51,66.3 55.37,73.16 71.37,73.16 72,73.78 v72,73.8 71.89,73.8
  Bottom 0.254: v72,73.8 71.37,73.16 57.4,73.16 52.32,78.24 52.32,96.27 46.23,102.37 LCD1.P$26
SFD  (via drill 0.5)
  Top 0.254: U1.38 28.45,62.69 30.48,61.73 41.91,61.73 43.69,63.51 50.29,63.51 50.55,63.76 54.86,68.08 76.71,68.08 v77.47,67.32 77.89,67.74 78.38,67.74 81.84,71.3 82.22,71.3 v82.24,71.51 | v80.52,83.57 89.41,83.57 90.17,84.33 R80.2
  Bottom 0.254: v80.52,83.57 80.52,73.41 v82.24,71.51 | COMMS_APP.8 75.44,65.28 v77.47,67.32
SIMO  (via drill 0.5)
  Top 0.254: 76.58,52.46 76.71,52.58 76.58,52.71 ISO2.6 76.58,50.93 75.95,50.3 69.85,50.3 69.09,49.54 69.09,44.96 64.01,39.88 v64.01,36.58 | v53.34,38.11 52.83,37.6 51.05,37.6 50.55,38.11 COMMS.1 50.29,38.87 49.28,37.85 49.28,35.82 48.51,35.06 46.99,35.06 44.7,32.77 44.7,26.17 46.76,24.11 U$1.P$21
  Bottom 0.254: v64.01,36.58 62.1,36.58 60.45,38.61 53.85,38.61 v53.34,38.11
SOMI  (via drill 0.5)
  Top 0.254: COMMS.3 46.74,37.6 46.74,35.82 43.94,33.03 43.94,25.91 46.39,23.46 U$1.P$22 | ISO2.7 77.85,51.44 76.2,49.79 71.63,49.79 v71.37,49.28
  Bottom 0.254: 48.01,38.61 COMMS.3 48.01,39.12 49.02,40.14 65.02,40.14 66.67,41.79 66.67,46.87 69.34,49.28 v71.37,49.28
SPI_CLK
  Top 0.254: 68.45,52.71 68.33,52.58 | 68.45,52.71 68.58,52.58 68.45,52.45 68.45,45.85 64.52,41.92 64.52,41.87 46.91,41.89 45.47,40.14 COMMS.5 44.2,37.6 44.2,35.57 43.43,34.8 43.43,25.41 46.03,22.81 U$1.P$23 | 68.45,52.71 ISO1.6
SPI_CS
  Top 0.254: 69.85,52.33 69.6,52.58 69.72,52.71 ISO1.7 69.79,52.78 69.85,52.84 | 69.85,52.84 69.73,52.96 | 69.85,52.84 69.71,52.97 69.71,54.64 69.22,55.12 66.55,55.12 65.79,54.36 65.79,44.2 64.01,42.42 46.48,42.42 COMMS.7 41.71,37.86 41.74,35.63 42.93,34.55 42.93,24.9 45.66,22.16 U$1.P$24
TCK  (via drill 0.5)
  Top 0.254: U1.95 24.95,81.54 24.89,81.54 24.64,81.79 23.37,81.79 22.61,82.56 v22.61,83.32
  Bottom 0.254: v22.61,83.32 22.61,96.78 21.84,97.54 21.84,100.08 JTAG2.7
TCK_AFE  (via drill 0.6)
  Top 0.254: U$1.P$10 60.27,28.01 60.71,28.45 60.71,30.23 62.71,32.23 66.52,32.23 v67.56,31.25 | JTAG1.7 84.58,31.25 v77.72,31.25
  Bottom 0.254: v67.56,31.25 v77.72,31.25
TDI
  Top 0.254: U1.93 25.93,82.34 24.61,83.73 24.64,89.16 26.92,91.45 26.92,99.83 28.19,101.1 JTAG2.3
TDO  (via drill 0.5)
  Top 0.254: v25.78,83.77 v25.78,83.76 26.45,83.09 U1.92
  Bottom 0.254: v25.78,83.77 25.91,90.18 25.91,90.68 24.38,92.21 24.38,94.5 25.27,95.39 27.56,95.39 29.46,97.29 29.46,100.08 JTAG2.1
TEST  (via drill 0.41, 0.6)
  Top 0.254: U1.91 26.95,82.07 v27.28,82.72 | JTAG2.8 25.91,96.02 v25.91,93.22
  Bottom 0.254: v27.28,82.72 27.28,91.45 v25.91,93.22
TMS  (via drill 0.5)
  Top 0.254: U1.94 25.45,81.75 23.62,83.57 v23.62,84.59
  Bottom 0.254: v23.62,84.59 23.62,94.75 24.38,95.51 24.38,100.08 JTAG2.5
TXD  (via drill 0.5)
  Top 0.406: R32.1 23.11,39.63 R31.2 21.51,39.71 v20.83,40.39
  Bottom 0.406: v20.83,40.39 17.02,40.39 16,41.41 16,46.49 13.41,49.08 CON1.2
U+
  Top 0.305: IC3.1 24.06,26.36 23.11,25.41 23.11,21.85
  Top 0.61: D10.2 15.09,21.85 19.39,21.85 | 19.39,21.85 C25.2 | 19.39,21.85 23.11,21.85 26.34,21.85 R23.1 | 19.39,21.85 19.39,19.73 C4.+
UART_RX  (via drill 0.5)
  Top 0.254: COMMS.2 50.55,35.57 49.28,34.3 47.24,34.3 45.47,32.52 45.47,26.42 47.12,24.76 U$1.P$20
  Top 0.406: U5.6 36.7,46.61 36.91,46.82 R39.2 39.45,46.82 | 39.45,46.82 39.62,47 R27.1 | v43.69,41.15 42.42,41.15 39.88,43.69 39.12,43.69 38.86,43.95 38.86,45.22 39.45,45.8 39.45,46.82
  Bottom 0.406: COMMS.2 50.55,36.58 49.53,37.6 46.99,37.6 46.74,37.85 46.74,40.39 45.97,41.15 v43.69,41.15
UART_TX  (via drill 0.5)
  Top 0.254: v47.24,33.03 45.97,31.5 45.97,27.44 v46.36,27.06 48,25.41 U$1.P$19 | R40.1 39.55,30.31 v39.88,29.98
  Bottom 0.254: v47.24,33.03 47.24,35.57 COMMS.4 | v39.88,29.98 39.88,28.45 41.4,27.06 v46.36,27.06
V1
  Top 0.61: R41.2 44.2,3.82 44.03,3.98 42.76,6.7
  Top 0.813: R44.1 42.76,6.7
V1+
  Top 0.254: U$1.P$8 56.93,26.71 56.39,26.17 56.39,16.52 54.86,14.99 C41.1
  Top 0.61: C41.1 48.86,14.83 48.77,14.74 48.86,14.65 C13.1 48.86,12.24 48.9,12.2 48.86,12.16 R50.2
  Top 0.813: C13.1 48.93,12.29 49.02,12.2 48.93,12.24
V1-
  Top 0.254: U$1.P$9 56.57,27.36 55.63,26.42 55.63,16.77 55.12,16.26 54.86,16.01 47.5,16.01 47.16,15.67 C41.2
  Top 0.813: R47.1 44.36,14.83 44.45,14.74 C14.2 C41.2
VBUS  (via drill 0.5)
  Top 0.254: U1.80 32.45,79.19 31.75,78.49 29.97,78.49 v28.88,77.73
  Bottom 0.254: 16.76,82.56 18.03,82.56 18.54,83.06 C43.1 18.63,83.48 18.67,83.44 19.68,83.44 20.32,84.08 20.32,88.4 18.29,90.43 14.48,90.43 14.22,90.18 | IC7.6 11.27,89.12 11.56,89.31 13.36,89.31 14.22,90.18 | D2.2 16.76,82.56 | 16.76,82.56 16.51,82.81 | 14.22,90.18 C42.1
  Bottom 0.61: v28.88,77.73 19.56,77.73 16.51,80.78 16.51,82.56 D2.2
VREF
  Top 0.254: U$1.P$7 61.36,26.06 61.72,26.42 C1.2 61.72,27.44
VREG_EN  (via drill 0.5, 0.6)
  Top 0.254: U1.41 29.92,63.66 30.61,63.25 41.15,63.25 42.93,65.03 49.02,65.03 55.88,71.89 72.64,71.89 73.41,72.65 73.41,74.43 74.17,75.19 v82.04,75.19 | v78.99,86.37 78.74,86.62 78.74,103.64 79.41,104.4 R108.1
  Bottom 0.254: v82.04,75.19 81.03,76.46 81.03,81.79 81.79,82.56 83.31,82.56 84.33,83.57 84.33,84.59 83.06,85.86 79.76,85.86 v78.99,86.37
VUSB
  Top 0.254: U1.81 31.95,81.23 32.26,81.54 | 37.85,94.24 38.06,94.28 R15.2
  Top 0.406: 32.26,81.54 36.83,81.54 38.61,83.32 38.61,93.86 38.1,94.37 37.85,94.24
XIN
  Top 0.254: XT1.P2 18.05,72.88 18.54,72.4 U1.13 | 15.49,73.16 15.41,73.08 XT1.P2 | C29.1 11.94,74.43 13.46,72.9 14.99,72.9 15.24,72.65 15.41,72.82 XT1.P2
XOUT
  Top 0.254: 17.53,70.38 XT1.P1 | 17.53,70.38 17.55,70.38 18.54,71.89 20.32,71.89 20.33,71.9 U1.14 | 17.53,70.38 17.53,70.36 17.78,70.11 C28.2
XT2IN
  Top 0.254: XT2.1 53.09,31.5 54.36,30.23 54.36,28.96 54.1,28.71 52.58,28.71 52.53,28.66 U$1.P$14
  Top 0.61: XT2.1 53.09,32.64 53,32.73 C16.2
XT2OUT
  Top 0.254: 58.17,32.39 58.17,32.26 54.18,28.04 U$1.P$15
  Top 0.61: XT2.3 58.17,32.39 58.25,32.48 C19.2

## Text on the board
_tplace: JTG_PWR2 | 1 | PWR2 | 1 | MSP430AFE Energy EVM | Mar 2012 | Ver 2.1 | 14 | R108 | 1 | R105 | DVCC2 | R106 | 2 | R107 | 1 | RF3 | R15 | JTAG2 | R84 | R77 | USB2 | C8 | R14 | C24 | R81 | R80 | R78 | + | R83 | R82 | C7 | R3 | Q1 | R79 | ZD3 | C37 | + | C32 | R4 | C29 | F66xx | U1 | C35 | XT1 | R87 | + | C44 | R85 | DGND2 | C45 | COMMS_APP | RF4 | R86 | 1 | 2,54 | C28 | + | SAFE AREA | C51 | 1 | 7 | + | LED2 | 5 | 9 | 5 | C20 | C46 | CAUTION UNSAFE AREA | C50 | REACT | L2 | C21 | R36 | R76 | C2 | CAUTION | OK2 | HDR2 | ISO2 | D3 | + | C54 | D4 | ISO3 | C22 | + | R73 | C55 | D1 | + | R72 | R75 | ISO1 | ACT | N2 | D7 | C15 | + | C52 | R27 | + | R39 | + | R29 | F09 | 6 | 1 | R30 | C53 | HDR1 | U5 | HIGH VOLTAGE | R37 | 7 | LED1 | 5 | 3 | 1 | OK1 | AREA | JTAG1 | DGND1 | R31 | C16 | CON1 | U2 | T1 | C19 | R32 | R28 | 1 | ZD1 | COMMS | XT2 | + | 1 | T2 | R40 | C12 | DVCC1 | C23 | + | C26 | 1 | R2 | IC3 | + | C10 | ZD2 | C9 | C1 | C11 | C25 | + | R61 | R23 | PWR1 | C17 | C30 | S4 | + | D10 | AFE | C18 | JTG_PWR1 | C34 | C27 | R17 | C33 | C14 | C41 | C31 | R18 | D32 | D33 | R21 | JMP1 | R33 | R34 | R20 | R47 | C13 | R16 | R19 | R53 | L15 | D24 | L17 | L18 | + | L16 | D29 | R26 | R44 | D22 | D26 | D28 | L5 | R24 | R50 | + | + | + | + | L6 | + | D23 | D27 | + | + | L1 | N1 | D25 | R38 | R41 | CUR1- | CUR2- | CUR1+ | CUR2+
_bplace: R6 | R7 | IC7 | C42 | C47 | C39 | R25 | R9 | + | C48 | C43 | C40 | D2 | R35 | C36 | C38 | + | C5 | C6 | 22 | 26 | VO- | VO+ | N | L | NC | R5 | R22 | 0817 | + | C4 | R1 | Ver 2.1 | MSP430AFE 1-Ph EVM | C49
